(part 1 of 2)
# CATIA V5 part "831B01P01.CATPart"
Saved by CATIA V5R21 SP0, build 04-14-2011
Part number: 831B01P01
Bounding box of the stored display mesh (mm): x -76.5 to 76.5, y -25.54 to 25.54, z -13.238 to 6.5
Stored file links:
  C:\Users\ALI OZGUN\Desktop\alhan\831B01P01.CATPart
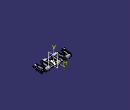
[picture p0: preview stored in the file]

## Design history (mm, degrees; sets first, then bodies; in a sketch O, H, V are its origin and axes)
Set1
  Extract1: ExtractElem start face of Pad3
  Extrapol1: ToExtrapol edge of Extract1, Support Extract1, Length 134
  Plane1: stored without definition
  Plane2: stored without definition
Body1 (main body)
  Sketch1 on yz-plane, origin (0, 0, 0), H (0, 1, 0), V (0, 0, 1)
    construction line L1 (-19.05, 0) -> (19.05, 0)
    point P1 (-19.05, 0)
    point P2 (19.05, 0)
    line L2 (-19.05, 6.5) -> (19.05, 6.5)
    line L3 (19.05, -6.5) -> (-19.05, -6.5)
    arc A1 centre (19.05, 0) radius 6.5 from (19.05, 6.5) to (19.05, -6.5) cw
    arc A2 centre (-19.05, 0) radius 6.5 from (-19.05, -6.5) to (-19.05, 6.5) cw
    circle A3 centre (19.05, 0) radius 3.25
    circle A4 centre (-19.05, 0) radius 3.25
    distance L1 L2 = 6.5
    length L1 = 38.1
    distance P2 V = 19.05
    radius A3 = 3.25
    radius A4 = 3.25
    coincidence: P1 H
    horizontal: L1 H
    tangency: A1 L2, A2 L2, A1 L3, A2 L3
  Pad1: profile Sketch1, direction (1, 0, 0), length 76.5, mirrored extent
  Sketch2 on face of Pad1 from Sketch1.L2, origin (0, 0, 6.5), H (1, 0, 0), V (0, 1, 0)
    line L1 (38, -14) -> (64, -14)
    line L2 (64, -14) -> (64, -36.0786)
    line L3 (64, -36.0786) -> (38, -36.0786)
    line L4 (38, -36.0786) -> (38, -14)
    line L5 (-13, -14) -> (13, -14)
    line L6 (13, -14) -> (13, -36.0786)
    line L7 (13, -36.0786) -> (-13, -36.0786)
    line L8 (-13, -36.0786) -> (-13, -14)
    point P7 (13, -36.0786)
    line L9 (-64, -14) -> (-38, -14)
    line L10 (-38, -14) -> (-38, -32.269)
    line L11 (-38, -32.269) -> (-64, -32.269)
    line L12 (-64, -32.269) -> (-64, -14)
    line L13 (85.7823, 31.3847) -> (63.5, 31.3847)
    line L14 (63.5, 31.3847) -> (63.5, 14)
    line L15 (63.5, 14) -> (85.7823, 14)
    line L16 (85.7823, 14) -> (85.7823, 31.3847)
    point P17 (12.5, 31.3847)
    line L17 (12.5, 31.3847) -> (38.5, 31.3847)
    line L18 (38.5, 31.3847) -> (38.5, 14)
    line L19 (38.5, 14) -> (12.5, 14)
    line L20 (12.5, 14) -> (12.5, 31.3847)
    point P19 (38.5, 14)
    line L21 (-38.5, 32.0801) -> (-12.5, 32.0801)
    line L22 (-12.5, 32.0801) -> (-12.5, 14)
    line L23 (-12.5, 14) -> (-38.5, 14)
    line L24 (-38.5, 14) -> (-38.5, 32.0801)
    point P23 (-12.5, 14)
    line L25 (-81.4786, 33.8185) -> (-63.5, 33.8185)
    line L26 (-63.5, 33.8185) -> (-63.5, 14)
    line L27 (-63.5, 14) -> (-81.4786, 14)
    line L28 (-81.4786, 14) -> (-81.4786, 33.8185)
    point P27 (-63.5, 14)
    reference projected line E1 (76.5, 19.05) -> (76.5, -19.05) from edge [face of Pad1 from Sketch1.L2 | end face of Pad1]
    reference projected line E2 (-76.5, 19.05) -> (-76.5, -19.05) from edge [start face of Pad1 | face of Pad1 from Sketch1.L2]
    reference projected line E3 (-76.5, 19.05) -> (-76.5, -19.05) from edge [start face of Pad1 | face of Pad1 from Sketch1.L2]
    reference projected line E4 (76.5, 19.05) -> (76.5, -19.05) from edge [face of Pad1 from Sketch1.L2 | end face of Pad1]
    distance L14 E1 = 13
    distance L26 E2 = 13
    distance L12 E3 = 12.5
    distance L2 E4 = 12.5
    distance L23 L5 = 28
    distance L5 H = 14
    distance L4 L2 = 26
    distance L12 L10 = 26
    distance L10 L8 = 25
    distance L6 L4 = 25
    distance L24 L26 = 25
    distance L18 L14 = 25
    distance L26 L22 = 51
    distance L20 L18 = 26
    horizontal: L1 H, L3 H, L5 H, L7 H, L9 H, L11 H, L13 H, L15 H, L17 H, L19 H, L21 H, L23 H, L25 H, L27 H
    vertical: L2 V, L4 V, L6 V, L8 V, L10 V, L12 V, L14 V, L16 V, L18 V, L20 V, L22 V, L24 V, L26 V, L28 V
    coincidence: P7 L3, P17 L13, P19 L15, P23 L15, P27 L15, L1 L5, L9 L5
  Pocket1: profile Sketch2, direction (0, 0, -1), length 53.5
  Sketch3 on end face of Pad1, origin (76.5, 0, 0), H (0, 1, 0), V (0, 0, 1)
    projected arc E1 centre (19.05, 0) radius 6.5 from (19.05, -6.5) to (19.05, 6.5) ccw from edge [face of Pocket1 from Sketch2.L14 | face of Pad1 from Sketch1.A1]
    projected arc E2 centre (19.05, 0) radius 6.5 from (19.05, -6.5) to (13.0358, 2.4657) ccw from edge [face of Pocket1 from Sketch2.L14 | face of Pad1 from Sketch1.A1]
    point P1 (19.05, -6.5)
    projected arc E3 centre (-19.05, 0) radius 6.5 from (-19.05, 6.5) to (-19.05, -6.5) ccw from edge [face of Pad1 from Sketch1.A2 | end face of Pad1]
    projected arc E4 centre (-19.05, 0) radius 6.5 from (-13.0358, 2.4657) to (-19.05, -6.5) ccw from edge [face of Pad1 from Sketch1.A2 | end face of Pad1]
    point P4 (-19.05, -6.5)
    projected line E5 (-19.05, -6.5) -> (14, -6.5) from edge [face of Pad1 from Sketch1.L3 | end face of Pad1]
    point P5 (-19.05, -6.5)
    projected line E6 (19.05, -6.5) -> (14, -6.5) from edge [face of Pocket1 from Sketch2.L14 | face of Pad1 from Sketch1.L3]
    point P7 (19.05, -6.5)
    line L1 (-13.0358, 2.4657) -> (-11, -2.5)
    line L2 (-11, -2.5) -> (11, -2.5)
    point P10 (11, -2.5)
    line L3 (11, -2.5) -> (13.0358, 2.4657)
    distance L2 E5 = 4
    length L2 = 22
    distance P10 V = 11
    horizontal: L2 H
    tangency: L3 E1, L1 E3
    coincidence: P1 P7, P4 P5
  Pocket2: profile Sketch3, direction (-1, 0, 0), length 172.5, outer side
  Sketch4 on face of Pocket2 from Sketch3.L2, origin (0, 0, -2.5), H (1, 0, 0), V (0, 1, 0)
    projected line E1 (38, -14) -> (38, -25.55) from edge [face of Pocket2 | face of Pocket1 from Sketch2.L4]
    projected line E2 (38, -14) -> (38, -19.05) from edge [face of Pocket2 | face of Pocket1 from Sketch2.L4]
    point P1 (38, -14)
    point P2 (38, -25.55)
    projected line E3 (13, -25.55) -> (13, -14) from edge [face of Pocket2 | face of Pocket1 from Sketch2.L6]
    projected line E4 (13, -19.05) -> (13, -14) from edge [face of Pocket2 | face of Pocket1 from Sketch2.L6]
    point P3 (13, -25.55)
    point P4 (13, -14)
    projected line E5 (64, -25.55) -> (64, -14) from edge [face of Pocket2 | face of Pocket1 from Sketch2.L2]
    projected line E6 (64, -19.05) -> (64, -14) from edge [face of Pocket2 | face of Pocket1 from Sketch2.L2]
    point P5 (64, -25.55)
    point P6 (64, -14)
    projected line E7 (38.5, 14) -> (38.5, 25.55) from edge [face of Pocket2 | face of Pocket1 from Sketch2.L18]
    projected line E8 (38.5, 14) -> (38.5, 19.05) from edge [face of Pocket2 | face of Pocket1 from Sketch2.L18]
    point P7 (38.5, 14)
    point P8 (38.5, 25.55)
    projected line E9 (63.5, 14) -> (63.5, 25.55) from edge [face of Pocket1 from Sketch2.L14 | face of Pocket2]
    projected line E10 (63.5, 14) -> (63.5, 19.05) from edge [face of Pocket1 from Sketch2.L14 | face of Pocket2]
    point P9 (63.5, 14)
    point P10 (63.5, 25.55)
    projected line E11 (12.5, 25.55) -> (12.5, 14) from edge [face of Pocket2 | face of Pocket1 from Sketch2.L20]
    projected line E12 (12.5, 19.05) -> (12.5, 14) from edge [face of Pocket2 | face of Pocket1 from Sketch2.L20]
    point P11 (12.5, 25.55)
    point P12 (12.5, 14)
    offset line E13 (9.5, 25.55) -> (9.5, 14) from edge [face of Pocket2 | face of Pocket1 from Sketch2.L20]
    offset line E14 (9.5, 19.05) -> (9.5, 14) from edge [face of Pocket2 | face of Pocket1 from Sketch2.L20]
    point P13 (9.5, 25.55)
    point P14 (9.5, 14)
    offset line E15 (16, -25.55) -> (16, -14) from edge [face of Pocket2 | face of Pocket1 from Sketch2.L6]
    offset line E16 (16, -19.05) -> (16, -14) from edge [face of Pocket2 | face of Pocket1 from Sketch2.L6]
    point P15 (16, -25.55)
    point P16 (16, -14)
    offset line E17 (35, -14) -> (35, -25.55) from edge [face of Pocket2 | face of Pocket1 from Sketch2.L4]
    offset line E18 (35, -14) -> (35, -19.05) from edge [face of Pocket2 | face of Pocket1 from Sketch2.L4]
    point P17 (35, -14)
    point P18 (35, -25.55)
    offset line E19 (41.5, 14) -> (41.5, 25.55) from edge [face of Pocket2 | face of Pocket1 from Sketch2.L18]
    offset line E20 (41.5, 14) -> (41.5, 19.05) from edge [face of Pocket2 | face of Pocket1 from Sketch2.L18]
    point P19 (41.5, 14)
    point P20 (41.5, 25.55)
    offset line E21 (60.5, 14) -> (60.5, 25.55) from edge [face of Pocket1 from Sketch2.L14 | face of Pocket2]
    offset line E22 (60.5, 14) -> (60.5, 19.05) from edge [face of Pocket1 from Sketch2.L14 | face of Pocket2]
    point P21 (60.5, 14)
    point P22 (60.5, 25.55)
    offset line E23 (67, -25.55) -> (67, -14) from edge [face of Pocket2 | face of Pocket1 from Sketch2.L2]
    offset line E24 (67, -19.05) -> (67, -14) from edge [face of Pocket2 | face of Pocket1 from Sketch2.L2]
    point P23 (67, -25.55)
    point P24 (67, -14)
    line L1 (13, -14) -> (9.5, 14)
    line L2 (16, -14) -> (12.5, 14)
    line L3 (35, -14) -> (38.5, 14)
    line L4 (38, -14) -> (41.5, 14)
    line L5 (64, -14) -> (60.5, 14)
    line L6 (67, -14) -> (63.5, 14)
    projected line E25 through (0, -19.05) direction (1, 0) from axis of face of Pocket2
    projected line E26 (13, -19.05) -> (16, -19.05) from axis of face of Pocket2
    projected line E27 (64, -19.05) -> (67, -19.05) from axis of face of Pocket2
    projected line E28 (35, -19.05) -> (38, -19.05) from axis of face of Pocket2
    point P25 (-10000000, -19.05)
    point P26 (10000000, -19.05)
    point P27 (67, -19.05)
    point P28 (38, -19.05)
    point P29 (64, -19.05)
    point P30 (64, -19.05)
    point P31 (38, -19.05)
    point P32 (35, -19.05)
    point P33 (16, -19.05)
    point P34 (35, -19.05)
    point P35 (16, -19.05)
    point P36 (13, -19.05)
    point P37 (13, -19.05)
    projected line E29 through (0, 19.05) direction (1, 0) from axis of face of Pocket2
    projected line E30 (9.5, 19.05) -> (12.5, 19.05) from axis of face of Pocket2
    projected line E31 (38.5, 19.05) -> (41.5, 19.05) from axis of face of Pocket2
    projected line E32 (60.5, 19.05) -> (63.5, 19.05) from axis of face of Pocket2
    point P38 (-10000000, 19.05)
    point P39 (10000000, 19.05)
    point P40 (63.5, 19.05)
    point P41 (9.5, 19.05)
    point P42 (9.5, 19.05)
    point P43 (12.5, 19.05)
    point P44 (12.5, 19.05)
    point P45 (38.5, 19.05)
    point P46 (38.5, 19.05)
    point P47 (41.5, 19.05)
    point P48 (60.5, 19.05)
    point P49 (41.5, 19.05)
    point P50 (60.5, 19.05)
    point P51 (-10000000, -19.05)
    point P52 (10000000, -19.05)
    point P53 (-10000000, 19.05)
    point P54 (10000000, 19.05)
    construction line L7 through (0, -19.05) direction (-1, 0)
    construction line L8 through (0, 19.05) direction (-1, 0)
    point P55 (-10000000, -19.05)
    point P56 (10000000, -19.05)
    point P57 (-16, -19.05)
    point P58 (-13, -19.05)
    point P59 (-67, -19.05)
    point P60 (-64, -19.05)
    point P61 (-38, -19.05)
    point P62 (-35, -19.05)
    point P63 (-38, -25.55)
    point P64 (-38, -14)
    point P65 (-38, -19.05)
    point P66 (-13, -14)
    point P67 (-13, -25.55)
    point P68 (-13, -19.05)
    point P69 (-64, -14)
    point P70 (-64, -25.55)
    point P71 (-64, -19.05)
    point P72 (-38.5, 25.55)
    point P73 (-38.5, 14)
    point P74 (-38.5, 19.05)
    point P75 (-63.5, 25.55)
    point P76 (-63.5, 14)
    point P77 (-63.5, 19.05)
    point P78 (-12.5, 14)
    point P79 (-12.5, 25.55)
    point P80 (-12.5, 19.05)
    point P81 (-9.5, 14)
    point P82 (-9.5, 25.55)
    point P83 (-9.5, 19.05)
    point P84 (-16, -14)
    point P85 (-16, -25.55)
    point P86 (-16, -19.05)
    point P87 (-35, -25.55)
    point P88 (-35, -14)
    point P89 (-35, -19.05)
    point P90 (-41.5, 25.55)
    point P91 (-41.5, 14)
    point P92 (-41.5, 19.05)
    point P93 (-60.5, 25.55)
    point P94 (-60.5, 14)
    point P95 (-60.5, 19.05)
    point P96 (-67, -14)
    point P97 (-67, -25.55)
    line L9 (-13, -14) -> (-9.5, 14)
    line L10 (-16, -14) -> (-12.5, 14)
    line L11 (-35, -14) -> (-38.5, 14)
    line L12 (-38, -14) -> (-41.5, 14)
    line L13 (-64, -14) -> (-60.5, 14)
    line L14 (-67, -14) -> (-63.5, 14)
    point P98 (-10000000, 19.05)
    point P99 (10000000, 19.05)
    point P100 (-12.5, 19.05)
    point P101 (-9.5, 19.05)
    point P102 (-41.5, 19.05)
    point P103 (-38.5, 19.05)
    point P104 (-60.5, 19.05)
    construction line L15 through (0, -19.05) direction (-1, 0)
    line L16 (-13, -19.05) -> (-16, -19.05)
    line L17 (-64, -19.05) -> (-67, -19.05)
    line L18 (-35, -19.05) -> (-38, -19.05)
    construction line L19 (-38, -14) -> (-38, -25.55)
    line L20 (-38, -14) -> (-38, -19.05)
    construction line L21 (-13, -25.55) -> (-13, -14)
    line L22 (-13, -19.05) -> (-13, -14)
    construction line L23 (-64, -25.55) -> (-64, -14)
    line L24 (-64, -19.05) -> (-64, -14)
    construction line L25 (-38.5, 14) -> (-38.5, 25.55)
    line L26 (-38.5, 14) -> (-38.5, 19.05)
    construction line L27 (-63.5, 14) -> (-63.5, 25.55)
    line L28 (-63.5, 14) -> (-63.5, 19.05)
    construction line L29 (-12.5, 25.55) -> (-12.5, 14)
    line L30 (-12.5, 19.05) -> (-12.5, 14)
    construction line L31 (-9.5, 25.55) -> (-9.5, 14)
    line L32 (-9.5, 19.05) -> (-9.5, 14)
    construction line L33 (-16, -25.55) -> (-16, -14)
    line L34 (-16, -19.05) -> (-16, -14)
    construction line L35 (-35, -14) -> (-35, -25.55)
    line L36 (-35, -14) -> (-35, -19.05)
    construction line L37 (-41.5, 14) -> (-41.5, 25.55)
    line L38 (-41.5, 14) -> (-41.5, 19.05)
    construction line L39 (-60.5, 14) -> (-60.5, 25.55)
    line L40 (-60.5, 14) -> (-60.5, 19.05)
    construction line L41 (-67, -25.55) -> (-67, -14)
    line L42 (-67, -19.05) -> (-67, -14)
    construction line L43 through (0, 19.05) direction (-1, 0)
    line L44 (-9.5, 19.05) -> (-12.5, 19.05)
    line L45 (-38.5, 19.05) -> (-41.5, 19.05)
    line L46 (-60.5, 19.05) -> (-63.5, 19.05)
    parallelism: L2 L1, L4 L3
    coincidence: E1 P28, E5 P29, E25 P30, E25 P31, E25 P32, E15 P33, E17 P34, E25 P35, E25 P36, E3 P37, E13 P41, E29 P42, E29 P43, E11 P44, E7 P45, E29 P46, E29 P47, E29 P48, E19 P49, E21 P50, P28 P31, P29 P30, P32 P34, P33 P35, P36 P37, P41 P42, P43 P44, P45 P46, P47 P49, P48 P50
    symmetry: P26 P51 V, P25 P52 V, E25 L7 V, P39 P53 V, P38 P54 V, E29 L8 V, P26 P55 V, P25 P56 V, P33 P57 V, P37 P58 V, P27 P59 V, P29 P60 V, P28 P61 V, P34 P62 V, E25 L15 V, P2 P63 V, P1 P64 V, P31 P65 V, E1 L19 V, P4 P66 V, P3 P67 V, P36 P68 V, E3 L21 V, P6 P69 V, P5 P70 V, P30 P71 V, E5 L23 V, P8 P72 V, P7 P73 V, P46 P74 V, E7 L25 V, P10 P75 V, P9 P76 V, P40 P77 V, E9 L27 V, P12 P78 V, P11 P79 V, P43 P80 V, E11 L29 V, P14 P81 V, P13 P82 V, P42 P83 V, E13 L31 V, P16 P84 V, P15 P85 V, P35 P86 V, E15 L33 V, P18 P87 V, P17 P88 V, P32 P89 V, E17 L35 V, P20 P90 V, P19 P91 V, P47 P92 V, E19 L37 V, P22 P93 V, P21 P94 V, P48 P95 V, E21 L39 V, P24 P96 V, P23 P97 V, E23 L41 V, L1 L9 V, L2 L10 V, L3 L11 V, L4 L12 V, L5 L13 V, L6 L14 V, P39 P98 V, P38 P99 V, P44 P100 V, P41 P101 V, P49 P102 V, P45 P103 V, P50 P104 V, E29 L43 V, E25 L18 V, E25 L17 V, E25 L16 V, E1 L20 V, E3 L22 V, E5 L24 V, E7 L26 V, E9 L28 V, E11 L30 V, E13 L32 V, E15 L34 V, E17 L36 V, E19 L38 V, E21 L40 V, E23 L42 V, E29 L46 V, E29 L45 V, E29 L44 V
  Pad2: profile Sketch4, direction (0, 0, 1), length 9
  Sketch5 on yz-plane, origin (0, 0, 0), H (0, 1, 0), V (0, 0, 1)
    projected circle E1 centre (-19.05, 0) radius 3.25 from edge [end face of Pad1 | face of Pad1 from Sketch1.A4]
    circle A1 centre (19.05, 0) radius 3.25
    reference projected circle E2 centre (19.05, 0) radius 3.25 from edge [face of Pad1 from Sketch1.A3 | face of Pad2]
    coincidence: A1 E2
  Pocket3: profile Sketch5, direction (-1, 0, 0), length 95, mirrored extent
  RemoveFace1: RemoveFaces (face of Pocket2 from Sketch3.L3; face of Pocket2; face of Pocket2 from Sketch3.L3; face of Pocket2; face of Pocket2 from Sketch3.L1; face of Pocket2; face of Pocket2 from Sketch3.L1; face of Pocket2; face of Pocket2; face of Pocket2; face of Pocket2; face of Pocket2 from Sketch3.L3; face of Pocket2 from Sketch3.L3; face of Pocket2 from Sketch3.L1)
  Chamfer1: length 4, angle 45, on edge [face of Pocket1 from Sketch2.L27 | face of Pocket2 from Sketch3.L2]; edge [face of Pocket1 from Sketch2.L9 | face of Pocket2 from Sketch3.L2]; edge [face of Pocket1 from Sketch2.L19 | face of Pocket2 from Sketch3.L2]; edge [face of Pocket1 from Sketch2.L5 | face of Pocket2 from Sketch3.L2]; edge [face of Pocket1 from Sketch2.L1 | face of Pocket2 from Sketch3.L2]; edge [face of Pocket1 from Sketch2.L15 | face of Pocket2 from Sketch3.L2]; edge [face of Pocket1 from Sketch2.L23 | face of Pocket2 from Sketch3.L2]
  Sketch6 on face of Pocket2 from Sketch3.L2, origin (0, 0, -2.5), H (1, 0, 0), V (0, 1, 0)
    point P1 (63.5, 19.05)
    point P2 (63.5, 25.55)
    line L1 (-10.8063, 3.55) -> (10.8062, 3.55)
    line L2 (-10.4313, 6.55) -> (10.4312, 6.55)
    construction line L3 (-27.6701, 3.55) -> (-27.6701, 6.55)
    construction line L4 (101.9815, 3.55) -> (101.9815, 6.55)
    point P7 (61.4312, 6.55)
    line L5 (40.5688, 6.55) -> (61.4312, 6.55)
    point P8 (40.5688, 6.55)
    line L6 (40.1938, 3.55) -> (61.8062, 3.55)
    point P13 (40.1938, 3.55)
    point P14 (61.8062, 3.55)
    line L7 (64.8062, 3.55) -> (72.5, 3.55)
    point P15 (64.8062, 3.55)
    line L8 (60.875, 11) -> (61.4312, 6.55)
    point P16 (60.875, 11)
    point P17 (63.5, -10)
    line L9 (63.5, -10) -> (38.5, -10)
    point P18 (38.5, -10)
    line L10 (38.5, -10) -> (40.1938, 3.55)
    point P19 (41.125, 11)
    line L11 (41.125, 11) -> (60.875, 11)
    line L12 (15.625, -11) -> (15.0687, -6.55)
    point P20 (15.625, -11)
    point P21 (13, 10)
    line L13 (13, 10) -> (38, 10)
    point P22 (38, 10)
    line L14 (38, 10) -> (36.3063, -3.55)
    point P23 (35.375, -11)
    line L15 (35.375, -11) -> (15.625, -11)
    line L16 (9.875, 11) -> (10.4312, 6.55)
    line L17 (12.5, -10) -> (-12.5, -10)
    line L18 (-12.5, -10) -> (-10.8063, 3.55)
    line L19 (-9.875, 11) -> (9.875, 11)
    line L20 (66, -6) -> (64.8062, 3.55)
    point P28 (66.625, -11)
    construction line L21 (76.5, 3.55) -> (76.5, -6)
    point P29 (76.5, -11)
    construction line L22 (76.5, -11) -> (66.625, -11)
    construction line L23 (63.5, 19.05) -> (63.5, 25.55)
    line L24 (40.5688, 6.55) -> (41.125, 11)
    line L25 (61.8062, 3.55) -> (63.5, -10)
    line L26 (14.6937, -3.55) -> (13, 10)
    line L27 (10.8062, 3.55) -> (12.5, -10)
    line L28 (-10.4313, 6.55) -> (-9.875, 11)
    line L29 (72.5, -6) -> (66, -6)
    point P30 (76.5, -6)
    point P31 (66.625, -6)
    construction line L30 (76.5, -11) -> (76.5, -6)
    construction line L31 (66.625, -11) -> (66.625, -6)
    point P32 (66, -6)
    point P33 (76.5, 3.55)
    point P34 (76.5, -6)
    point P35 (-63.5, 25.55)
    point P36 (-63.5, 19.05)
    construction line L32 (-63.5, 19.05) -> (-63.5, 25.55)
    point P37 (-66.625, -11)
    point P38 (-76.5, -11)
    construction line L33 (-76.5, -11) -> (-66.625, -11)
    point P39 (-61.4312, 6.55)
    point P40 (-40.5688, 6.55)
    line L34 (-40.5688, 6.55) -> (-61.4312, 6.55)
    point P41 (-61.8062, 3.55)
    point P42 (-40.1938, 3.55)
    line L35 (-40.1938, 3.55) -> (-61.8062, 3.55)
    point P43 (-64.8062, 3.55)
    line L36 (-64.8062, 3.55) -> (-72.5, 3.55)
    point P44 (-60.875, 11)
    line L37 (-60.875, 11) -> (-61.4312, 6.55)
    point P45 (-38.5, -10)
    point P46 (-63.5, -10)
    line L38 (-63.5, -10) -> (-38.5, -10)
    line L39 (-38.5, -10) -> (-40.1938, 3.55)
    point P47 (-41.125, 11)
    line L40 (-41.125, 11) -> (-60.875, 11)
    point P48 (-15.625, -11)
    line L41 (-15.625, -11) -> (-15.0687, -6.55)
    point P49 (-38, 10)
    point P50 (-13, 10)
    line L42 (-13, 10) -> (-38, 10)
    line L43 (-38, 10) -> (-36.3063, -3.55)
    point P51 (-35.375, -11)
    line L44 (-35.375, -11) -> (-15.625, -11)
    point P52 (-66, -6)
    line L45 (-66, -6) -> (-64.8062, 3.55)
    line L46 (-40.5688, 6.55) -> (-41.125, 11)
    line L47 (-61.8062, 3.55) -> (-63.5, -10)
    line L48 (-14.6937, -3.55) -> (-13, 10)
    line L49 (-72.5, -6) -> (-66, -6)
    line L50 (72.5, 3.55) -> (72.5, -6)
    point P53 (72.5, 3.55)
    point P54 (72.5, -6)
    construction line L51 (76.5, 3.55) -> (72.5, 3.55)
    construction line L52 (76.5, -6) -> (72.5, -6)
    point P55 (72.5, 3.55)
    point P56 (72.5, -6)
    point P57 (-72.5, -6)
    point P58 (-72.5, 3.55)
    line L53 (-72.5, 3.55) -> (-72.5, -6)
    line L54 (-15.0687, -6.55) -> (-35.9313, -6.55)
    line L55 (-14.6937, -3.55) -> (-36.3063, -3.55)
    line L56 (15.0687, -6.55) -> (35.9313, -6.55)
    line L57 (14.6937, -3.55) -> (36.3063, -3.55)
    line L58 (35.9313, -6.55) -> (35.375, -11)
    line L59 (-35.9313, -6.55) -> (-35.375, -11)
    distance P2 L1 = 22
    distance L1 L2 = 3
    distance L22 L29 = 5
    distance L21 L50 = 4
    horizontal: L1 H, L6 H, L7 H
    perpendicularity: L3 L1, L3 L2, L4 L1, L4 L2, L30 L22, L30 L29, L31 L22, L31 L29, L51 L21, L51 L50, L52 L21, L52 L50
    coincidence: L2 L5, L6 L7, L10 L24, L8 L25, L12 L26, L16 L27, L18 L28, P28 L20, P31 L29, P29 L21, P30 L29, P33 L7, P53 L50, P34 L29, P54 L50
    fix: L23, P2, L22
    symmetry: P2 P35 V, P1 P36 V, L23 L32 V, P28 P37 V, P29 P38 V, L22 L33 V, P7 P39 V, P8 P40 V, L5 L34 V, P14 P41 V, P13 P42 V, L6 L35 V, P15 P43 V, L7 L36 V, P16 P44 V, L8 L37 V, P18 P45 V, P17 P46 V, L9 L38 V, L10 L39 V, P19 P47 V, L11 L40 V, P20 P48 V, L12 L41 V, P22 P49 V, P21 P50 V, L13 L42 V, L14 L43 V, P23 P51 V, L15 L44 V, P32 P52 V, L20 L45 V, L24 L46 V, L25 L47 V, L26 L48 V, L29 L49 V, P56 P57 V, P55 P58 V, L50 L53 V
  Pocket4: profile Sketch6, direction (0, 0, -1), length 9, mirrored extent
  Body2
    Sketch7 on face of Pocket2, origin (0, 0, -6.5), H (1, 0, 0), V (0, -1, 0)
      point P1 (-60.75, 15)
      line L1 (-60.75, 15) -> (-54.25, 15)
      line L2 (-54.25, 15) -> (-54.25, -15)
      line L3 (-54.25, -15) -> (-60.75, -15)
      line L4 (-60.75, -15) -> (-60.75, 15)
      point P2 (-54.25, 15)
      point P3 (-54.25, -15)
      point P4 (-60.75, -15)
      point P5 (-47.75, 15)
      line L5 (-47.75, 15) -> (-41.25, 15)
      line L6 (-41.25, 15) -> (-41.25, -15)
      line L7 (-41.25, -15) -> (-47.75, -15)
      line L8 (-47.75, -15) -> (-47.75, 15)
      point P6 (-41.25, 15)
      point P7 (-41.25, -15)
      point P8 (-47.75, -15)
      reference projected line E1 (-64, 19.05) -> (-64, 14) from edge [face of Pocket2 | face of Pad2]
      reference projected line E2 (-38, 19.05) -> (-38, 14) from edge [face of Pad2 | face of Pocket2]
      point P9 (-38, 19.05)
      point P10 (-38, 14)
      point P11 (-15.25, 15)
      point P12 (-21.75, 15)
      point P13 (-21.75, -15)
      point P14 (-15.25, -15)
      point P15 (-28.25, 15)
      point P16 (-34.75, 15)
      point P17 (-34.75, -15)
      point P18 (-28.25, -15)
      line L9 (-15.25, 15) -> (-21.75, 15)
      line L10 (-21.75, 15) -> (-21.75, -15)
      line L11 (-21.75, -15) -> (-15.25, -15)
      line L12 (-15.25, -15) -> (-15.25, 15)
      line L13 (-28.25, 15) -> (-34.75, 15)
      line L14 (-34.75, 15) -> (-34.75, -15)
      line L15 (-34.75, -15) -> (-28.25, -15)
      line L16 (-28.25, -15) -> (-28.25, 15)
      reference projected line E3 (-13, 19.05) -> (-13, 14) from edge [face of Pocket2 | face of Pad2]
      point P19 (-13, 19.05)
      point P20 (-13, 14)
      point P21 (-10.75, 15)
      point P22 (-4.25, 15)
      point P23 (-4.25, -15)
      point P24 (-10.75, -15)
      construction line L17 (-10.75, 15) -> (-4.25, 15)
      construction line L18 (-4.25, 15) -> (-4.25, -15)
      construction line L19 (-4.25, -15) -> (-10.75, -15)
      construction line L20 (-10.75, -15) -> (-10.75, 15)
      point P25 (60.75, 15)
      point P26 (54.25, 15)
      point P27 (54.25, -15)
      point P28 (60.75, -15)
      point P29 (47.75, 15)
      point P30 (41.25, 15)
      point P31 (41.25, -15)
      point P32 (47.75, -15)
      point P33 (38, 14)
      point P34 (38, 19.05)
      point P35 (15.25, 15)
      point P36 (21.75, 15)
      point P37 (21.75, -15)
      point P38 (15.25, -15)
      point P39 (28.25, 15)
      point P40 (34.75, 15)
      point P41 (34.75, -15)
      point P42 (28.25, -15)
      point P43 (13, 14)
      point P44 (13, 19.05)
      point P45 (10.75, 15)
      point P46 (4.25, 15)
      point P47 (4.25, -15)
      point P48 (10.75, -15)
      line L21 (60.75, 15) -> (54.25, 15)
      line L22 (54.25, 15) -> (54.25, -15)
      line L23 (54.25, -15) -> (60.75, -15)
      line L24 (60.75, -15) -> (60.75, 15)
      line L25 (47.75, 15) -> (41.25, 15)
      line L26 (41.25, 15) -> (41.25, -15)
      line L27 (41.25, -15) -> (47.75, -15)
      line L28 (47.75, -15) -> (47.75, 15)
      line L29 (15.25, 15) -> (21.75, 15)
      line L30 (21.75, 15) -> (21.75, -15)
      line L31 (21.75, -15) -> (15.25, -15)
      line L32 (15.25, -15) -> (15.25, 15)
      line L33 (28.25, 15) -> (34.75, 15)
      line L34 (34.75, 15) -> (34.75, -15)
      line L35 (34.75, -15) -> (28.25, -15)
      line L36 (28.25, -15) -> (28.25, 15)
      construction line L37 (10.75, 15) -> (4.25, 15)
      construction line L38 (4.25, 15) -> (4.25, -15)
      construction line L39 (4.25, -15) -> (10.75, -15)
      construction line L40 (10.75, -15) -> (10.75, 15)
      construction line L41 (38, 19.05) -> (38, 14)
      construction line L42 (13, 19.05) -> (13, 14)
      point P49 (-74.2, 15)
      line L43 (-74.2, 15) -> (-67.7, 15)
      line L44 (-67.7, 15) -> (-67.7, -15)
      line L45 (-67.7, -15) -> (-74.2, -15)
      line L46 (-74.2, -15) -> (-74.2, 15)
      point P50 (-67.7, 15)
      point P51 (-67.7, -15)
      point P52 (-74.2, -15)
      reference projected line E4 (-76.5, 19.05) -> (-76.5, -14) from edge [start face of Pad1 | face of Pocket2]
      point P53 (74.2, 15)
      point P54 (67.7, 15)
      point P55 (67.7, -15)
      point P56 (74.2, -15)
      line L47 (74.2, 15) -> (67.7, 15)
      line L48 (67.7, 15) -> (67.7, -15)
      line L49 (67.7, -15) -> (74.2, -15)
      line L50 (74.2, -15) -> (74.2, 15)
      point P57 (-9.75, 15)
      line L51 (-9.75, 15) -> (-3.25, 15)
      line L52 (-3.25, 15) -> (-3.25, -15)
      line L53 (-3.25, -15) -> (-9.75, -15)
      line L54 (-9.75, -15) -> (-9.75, 15)
      point P58 (-3.25, 15)
      point P59 (-3.25, -15)
      point P60 (-9.75, -15)
      point P61 (9.75, -15)
      point P62 (3.25, -15)
      point P63 (3.25, 15)
      point P64 (9.75, 15)
      line L55 (9.75, -15) -> (9.75, 15)
      line L56 (3.25, -15) -> (9.75, -15)
      line L57 (3.25, 15) -> (3.25, -15)
      line L58 (9.75, 15) -> (3.25, 15)
      length L1 = 6.5
      distance L8 L6 = 6.5
      distance L6 L4 = 19.5
      distance L4 E1 = 3.25
      distance L7 L5 = 30
      distance L5 H = 15
      length L43 = 6.5
      distance L44 E4 = 8.8
      distance L54 L52 = 6.5
      distance L52 V = 3.25
      horizontal: L1 H, L3 H, L5 H, L7 H, L43 H, L45 H, L51 H, L53 H
      vertical: L2 V, L4 V, L6 V, L8 V, L44 V, L46 V, L52 V, L54 V
      coincidence: P5 L1, P7 L3, P49 L37, P51 L39, P57 L17, P59 L45
      symmetry: P1 P11 E2, P2 P12 E2, P3 P13 E2, P4 P14 E2, P5 P15 E2, P6 P16 E2, P7 P17 E2, P8 P18 E2, L1 L9 E2, L2 L10 E2, L3 L11 E2, L4 L12 E2, L5 L13 E2, L6 L14 E2, L7 L15 E2, L8 L16 E2, P11 P21 E3, P12 P22 E3, P13 P23 E3, P14 P24 E3, L9 L17 E3, L10 L18 E3, L11 L19 E3, L12 L20 E3, P1 P25 V, P2 P26 V, P3 P27 V, P4 P28 V, P5 P29 V, P6 P30 V, P7 P31 V, P8 P32 V, P10 P33 V, P9 P34 V, E2 L41 V, P11 P35 V, P12 P36 V, P13 P37 V, P14 P38 V, P15 P39 V, P16 P40 V, P17 P41 V, P18 P42 V, P20 P43 V, P19 P44 V, E3 L42 V, P21 P45 V, P22 P46 V, P23 P47 V, P24 P48 V, L1 L21 V, L2 L22 V, L3 L23 V, L4 L24 V, L5 L25 V, L6 L26 V, L7 L27 V, L8 L28 V, L9 L29 V, L10 L30 V, L11 L31 V, L12 L32 V, L13 L33 V, L14 L34 V, L15 L35 V, L16 L36 V, L17 L37 V, L18 L38 V, L19 L39 V, L20 L40 V, P49 P53 V, P50 P54 V, P51 P55 V, P52 P56 V, L43 L47 V, L44 L48 V, L45 L49 V, L46 L50 V, P60 P61 V, P59 P62 V, P58 P63 V, P57 P64 V, L54 L55 V, L53 L56 V, L52 L57 V, L51 L58 V
    Pad3: profile Sketch7, direction (0, 0, -1), length 6.5
    Align1: SewingRemoveFace face of Pad3 from Sketch7.L35, SplitPlane face of Chamfer1
    Align2: SewingRemoveFace face of Pad3 from Sketch7.L31, SplitPlane face of Chamfer1
    Align3: SewingRemoveFace face of Pad3 from Sketch7.L49, SplitPlane face of Chamfer1
    Align4: SewingRemoveFace face of Pad3 from Sketch7.L11, SplitPlane face of Chamfer1
    Align5: SewingRemoveFace face of Pad3 from Sketch7.L15, SplitPlane face of Chamfer1
    Align6: SewingRemoveFace face of Pad3 from Sketch7.L45, SplitPlane face of Chamfer1
    Align7: SewingRemoveFace face of Pad3 from Sketch7.L1, SplitPlane face of Chamfer1
    Align8: SewingRemoveFace face of Pad3 from Sketch7.L5, SplitPlane face of Chamfer1
    Align9: SewingRemoveFace face of Pad3 from Sketch7.L51, SplitPlane face of Chamfer1
    Align10: SewingRemoveFace face of Pad3 from Sketch7.L58, SplitPlane face of Chamfer1
    Align11: SewingRemoveFace face of Pad3 from Sketch7.L21, SplitPlane face of Chamfer1
    Align12: SewingRemoveFace face of Pad3 from Sketch7.L25, SplitPlane face of Chamfer1
    Draft1: Angle 45, Neutral Extrapol1, PullDir Extrapol1, SupportToDraft (face of Pad3 from Sketch7.L43; face of Pad3 from Sketch7.L13; face of Pad3 from Sketch7.L9; face of Pad3 from Sketch7.L29; face of Pad3 from Sketch7.L33; face of Pad3 from Sketch7.L47)
    Draft2: Angle 45, Neutral Extrapol1, PullDir Extrapol1, SupportToDraft (face of Pad3 from Sketch7.L7; face of Pad3 from Sketch7.L3; face of Pad3 from Sketch7.L27; face of Pad3 from Sketch7.L23; face of Pad3 from Sketch7.L53; face of Pad3 from Sketch7.L56)
    Thickness1: Face (face of Pad3 from Sketch7.L47; face of Pad3 from Sketch7.L33; face of Pad3 from Sketch7.L29; face of Pad3 from Sketch7.L9; face of Pad3 from Sketch7.L13; face of Pad3 from Sketch7.L43; face of Pad3 from Sketch7.L23; face of Pad3 from Sketch7.L27; face of Pad3 from Sketch7.L56; face of Pad3 from Sketch7.L53; face of Pad3 from Sketch7.L7; face of Pad3 from Sketch7.L3), Thickness 2
    Sketch8 on end face of Pad3, origin (0, 0, -13), H (1, 0, 0), V (0, -1, 0)
      construction line L1 (-57.5, 32.3998) -> (-57.5, 10.4716)
      line L2 (-56.2, 32.3998) -> (-56.2, 10.4716)
      line L3 (-58.8, 10.4716) -> (-58.8, 32.3998)
      arc A1 centre (-57.5, 10.4716) radius 1.3 from (-56.2, 10.4716) to (-58.8, 10.4716) cw
      arc A2 centre (-57.5, 32.3998) radius 1.3 from (-58.8, 32.3998) to (-56.2, 32.3998) cw
      point P3 (-56.2, 32.3998)
      point P4 (-56.2, 10.4716)
      point P5 (-58.8, 10.4716)
      point P6 (-58.8, 32.3998)
      construction line L4 (-57.5, 4.8716) -> (-57.5, -8.5284)
      line L5 (-56.2, 4.8716) -> (-56.2, -8.5284)
      line L6 (-58.8, -8.5284) -> (-58.8, 4.8716)
      arc A3 centre (-57.5, -8.5284) radius 1.3 from (-56.2, -8.5284) to (-58.8, -8.5284) cw
      arc A4 centre (-57.5, 4.8716) radius 1.3 from (-58.8, 4.8716) to (-56.2, 4.8716) cw
      point P9 (-56.2, 4.8716)
      point P10 (-56.2, -8.5284)
      point P11 (-58.8, -8.5284)
      point P12 (-58.8, 4.8716)
      reference projected line E1 (-54.25, -15) -> (-54.25, 15) from edge [face of Pad3 from Sketch7.L2 | end face of Pad3]
      construction line L7 (-51, 29.4802) -> (-51, -21.867)
      point P13 (-51, 29.4802)
      reference projected line E2 (-47.75, 15) -> (-47.75, -15) from edge [face of Pad3 from Sketch7.L8 | end face of Pad3]
      construction line L8 (-44.5, 32.3998) -> (-44.5, 10.4716)
      construction line L9 (-44.5, 4.8716) -> (-44.5, -8.5284)
      point P19 (-45.8, 10.4716)
      point P20 (-45.8, 32.3998)
      line L10 (-45.8, 32.3998) -> (-45.8, 10.4716)
      point P21 (-43.2, 32.3998)
      point P22 (-43.2, 10.4716)
      line L11 (-43.2, 10.4716) -> (-43.2, 32.3998)
      arc A5 centre (-44.5, 10.4716) radius 1.3 from (-45.8, 10.4716) to (-43.2, 10.4716) ccw
      arc A6 centre (-44.5, 32.3998) radius 1.3 from (-43.2, 32.3998) to (-45.8, 32.3998) ccw
      point P23 (-45.8, -8.5284)
      point P24 (-45.8, 4.8716)
      line L12 (-45.8, 4.8716) -> (-45.8, -8.5284)
      point P25 (-43.2, 4.8716)
      point P26 (-43.2, -8.5284)
      line L13 (-43.2, -8.5284) -> (-43.2, 4.8716)
      arc A7 centre (-44.5, -8.5284) radius 1.3 from (-45.8, -8.5284) to (-43.2, -8.5284) ccw
      arc A8 centre (-44.5, 4.8716) radius 1.3 from (-43.2, 4.8716) to (-45.8, 4.8716) ccw
      construction line L14 (57.5, 32.3998) -> (57.5, 10.4716)
      point P29 (56.2, 32.3998)
      point P30 (56.2, 10.4716)
      point P31 (58.8, 10.4716)
      point P32 (58.8, 32.3998)
      construction line L15 (57.5, 4.8716) -> (57.5, -8.5284)
      point P35 (56.2, 4.8716)
      point P36 (56.2, -8.5284)
      point P37 (58.8, -8.5284)
      point P38 (58.8, 4.8716)
      point P39 (51, 29.4802)
      construction line L16 (44.5, 32.3998) -> (44.5, 10.4716)
      construction line L17 (44.5, 4.8716) -> (44.5, -8.5284)
      point P44 (45.8, 10.4716)
      point P45 (45.8, 32.3998)
      point P46 (43.2, 32.3998)
      point P47 (43.2, 10.4716)
      point P48 (45.8, -8.5284)
      point P49 (45.8, 4.8716)
      point P50 (43.2, 4.8716)
      point P51 (43.2, -8.5284)
      line L18 (56.2, 32.3998) -> (56.2, 10.4716)
      line L19 (58.8, 10.4716) -> (58.8, 32.3998)
      arc A9 centre (57.5, 10.4716) radius 1.3 from (56.2, 10.4716) to (58.8, 10.4716) ccw
      arc A10 centre (57.5, 32.3998) radius 1.3 from (58.8, 32.3998) to (56.2, 32.3998) ccw
      line L20 (56.2, 4.8716) -> (56.2, -8.5284)
      line L21 (58.8, -8.5284) -> (58.8, 4.8716)
      arc A11 centre (57.5, -8.5284) radius 1.3 from (56.2, -8.5284) to (58.8, -8.5284) ccw
      arc A12 centre (57.5, 4.8716) radius 1.3 from (58.8, 4.8716) to (56.2, 4.8716) ccw
      line L22 (45.8, 32.3998) -> (45.8, 10.4716)
      line L23 (43.2, 10.4716) -> (43.2, 32.3998)
      arc A13 centre (44.5, 10.4716) radius 1.3 from (45.8, 10.4716) to (43.2, 10.4716) cw
      arc A14 centre (44.5, 32.3998) radius 1.3 from (43.2, 32.3998) to (45.8, 32.3998) cw
      line L24 (45.8, 4.8716) -> (45.8, -8.5284)
      line L25 (43.2, -8.5284) -> (43.2, 4.8716)
      arc A15 centre (44.5, -8.5284) radius 1.3 from (45.8, -8.5284) to (43.2, -8.5284) cw
      arc A16 centre (44.5, 4.8716) radius 1.3 from (43.2, 4.8716) to (45.8, 4.8716) cw
      construction line L26 (-25.5, 35.6086) -> (-25.5, -36.7002)
      point P53 (-25.5, -36.7002)
      reference projected line E3 (-9.75, 15) -> (-9.75, -15) from edge [face of Pad3 from Sketch7.L54 | end face of Pad3]
      construction line L27 (6.5, 32.3998) -> (6.5, 10.4716)
      construction line L28 (6.5, 4.8716) -> (6.5, -8.5284)
      construction line L29 (-6.5, 32.3998) -> (-6.5, 10.4716)
      construction line L30 (-6.5, 4.8716) -> (-6.5, -8.5284)
      point P62 (5.2, 10.4716)
      point P63 (5.2, 32.3998)
      line L31 (5.2, 32.3998) -> (5.2, 10.4716)
      point P64 (7.8, 32.3998)
      point P65 (7.8, 10.4716)
      line L32 (7.8, 10.4716) -> (7.8, 32.3998)
      arc A17 centre (6.5, 10.4716) radius 1.3 from (5.2, 10.4716) to (7.8, 10.4716) ccw
      arc A18 centre (6.5, 32.3998) radius 1.3 from (7.8, 32.3998) to (5.2, 32.3998) ccw
      point P66 (5.2, -8.5284)
      point P67 (5.2, 4.8716)
      line L33 (5.2, 4.8716) -> (5.2, -8.5284)
      point P68 (7.8, 4.8716)
      point P69 (7.8, -8.5284)
      line L34 (7.8, -8.5284) -> (7.8, 4.8716)
      arc A19 centre (6.5, -8.5284) radius 1.3 from (5.2, -8.5284) to (7.8, -8.5284) ccw
      arc A20 centre (6.5, 4.8716) radius 1.3 from (7.8, 4.8716) to (5.2, 4.8716) ccw
      point P70 (-5.2, 10.4716)
      point P71 (-5.2, 32.3998)
      line L35 (-5.2, 32.3998) -> (-5.2, 10.4716)
      point P72 (-7.8, 32.3998)
      point P73 (-7.8, 10.4716)
      line L36 (-7.8, 10.4716) -> (-7.8, 32.3998)
      arc A21 centre (-6.5, 10.4716) radius 1.3 from (-5.2, 10.4716) to (-7.8, 10.4716) cw
      arc A22 centre (-6.5, 32.3998) radius 1.3 from (-7.8, 32.3998) to (-5.2, 32.3998) cw
      point P74 (-5.2, -8.5284)
      point P75 (-5.2, 4.8716)
      line L37 (-5.2, 4.8716) -> (-5.2, -8.5284)
      point P76 (-7.8, 4.8716)
      point P77 (-7.8, -8.5284)
      line L38 (-7.8, -8.5284) -> (-7.8, 4.8716)
      arc A23 centre (-6.5, -8.5284) radius 1.3 from (-5.2, -8.5284) to (-7.8, -8.5284) cw
      arc A24 centre (-6.5, 4.8716) radius 1.3 from (-7.8, 4.8716) to (-5.2, 4.8716) cw
      axis line L39 (-38, 43.1227) -> (-38, -25.9192)
      reference projected line E4 (-34.75, 15) -> (-34.75, -15) from edge [face of Pad3 from Sketch7.L14 | end face of Pad3]
      reference projected line E5 (-34.75, 8.5) -> (-34.75, 15) from edge [face of Pad3 from Sketch7.L13 | face of Pad3 from Sketch7.L14]
      reference projected line E6 (-41.25, -15) -> (-41.25, 15) from edge [face of Pad3 from Sketch7.L6 | end face of Pad3]
      construction line L40 (-18.5, -32.3998) -> (-18.5, -10.4716)
      point P82 (-18.5, 8.5284)
      construction line L41 (-18.5, -4.8716) -> (-18.5, 8.5284)
      construction line L42 (-31.5, -29.4713) -> (-31.5, -10.4716)
      point P86 (-31.5, 8.5284)
      construction line L43 (-31.5, -4.8716) -> (-31.5, 8.5284)
      point P88 (-19.8, -10.4716)
      point P89 (-19.8, -32.3998)
      line L44 (-19.8, -32.3998) -> (-19.8, -10.4716)
      point P90 (-17.2, -32.3998)
      point P91 (-17.2, -10.4716)
      line L45 (-17.2, -10.4716) -> (-17.2, -32.3998)
      arc A25 centre (-18.5, -10.4716) radius 1.3 from (-19.8, -10.4716) to (-17.2, -10.4716) cw
      arc A26 centre (-18.5, -32.3998) radius 1.3 from (-17.2, -32.3998) to (-19.8, -32.3998) cw
      point P92 (-19.8, 8.5284)
      point P93 (-19.8, -4.8716)
      line L46 (-19.8, -4.8716) -> (-19.8, 8.5284)
      point P94 (-17.2, -4.8716)
      point P95 (-17.2, 8.5284)
      line L47 (-17.2, 8.5284) -> (-17.2, -4.8716)
      arc A27 centre (-18.5, 8.5284) radius 1.3 from (-19.8, 8.5284) to (-17.2, 8.5284) cw
      arc A28 centre (-18.5, -4.8716) radius 1.3 from (-17.2, -4.8716) to (-19.8, -4.8716) cw
      point P96 (-30.2, -10.4716)
      point P97 (-30.2, -29.4713)
      line L48 (-30.2, -29.4713) -> (-30.2, -10.4716)
      point P98 (-32.8, -29.4713)
      point P99 (-32.8, -10.4716)
      line L49 (-32.8, -10.4716) -> (-32.8, -29.4713)
      arc A29 centre (-31.5, -10.4716) radius 1.3 from (-30.2, -10.4716) to (-32.8, -10.4716) ccw
      arc A30 centre (-31.5, -29.4713) radius 1.3 from (-32.8, -29.4713) to (-30.2, -29.4713) ccw
      point P100 (-30.2, 8.5284)
      point P101 (-30.2, -4.8716)
      line L50 (-30.2, -4.8716) -> (-30.2, 8.5284)
      point P102 (-32.8, -4.8716)
      point P103 (-32.8, 8.5284)
      line L51 (-32.8, 8.5284) -> (-32.8, -4.8716)
      arc A31 centre (-31.5, 8.5284) radius 1.3 from (-30.2, 8.5284) to (-32.8, 8.5284) ccw
      arc A32 centre (-31.5, -4.8716) radius 1.3 from (-32.8, -4.8716) to (-30.2, -4.8716) ccw
      point P104 (25.5, -36.7002)
      construction line L52 (18.5, -32.3998) -> (18.5, -10.4716)
      construction line L53 (18.5, -4.8716) -> (18.5, 8.5284)
      construction line L54 (31.5, -29.4713) -> (31.5, -10.4716)
      construction line L55 (31.5, -4.8716) -> (31.5, 8.5284)
      point P113 (19.8, -10.4716)
      point P114 (19.8, -32.3998)
      point P115 (17.2, -32.3998)
      point P116 (17.2, -10.4716)
      point P117 (19.8, 8.5284)
      point P118 (19.8, -4.8716)
      point P119 (17.2, -4.8716)
      point P120 (17.2, 8.5284)
      point P121 (30.2, -10.4716)
      point P122 (30.2, -29.4713)
      point P123 (32.8, -29.4713)
      point P124 (32.8, -10.4716)
      point P125 (30.2, 8.5284)
      point P126 (30.2, -4.8716)
      point P127 (32.8, -4.8716)
      point P128 (32.8, 8.5284)
      line L56 (19.8, -32.3998) -> (19.8, -10.4716)
      line L57 (17.2, -10.4716) -> (17.2, -32.3998)
      arc A33 centre (18.5, -10.4716) radius 1.3 from (19.8, -10.4716) to (17.2, -10.4716) ccw
      arc A34 centre (18.5, -32.3998) radius 1.3 from (17.2, -32.3998) to (19.8, -32.3998) ccw
      line L58 (19.8, -4.8716) -> (19.8, 8.5284)
      line L59 (17.2, 8.5284) -> (17.2, -4.8716)
      arc A35 centre (18.5, 8.5284) radius 1.3 from (19.8, 8.5284) to (17.2, 8.5284) ccw
      arc A36 centre (18.5, -4.8716) radius 1.3 from (17.2, -4.8716) to (19.8, -4.8716) ccw
      line L60 (30.2, -29.4713) -> (30.2, -10.4716)
      line L61 (32.8, -10.4716) -> (32.8, -29.4713)
      arc A37 centre (31.5, -10.4716) radius 1.3 from (30.2, -10.4716) to (32.8, -10.4716) cw
      arc A38 centre (31.5, -29.4713) radius 1.3 from (32.8, -29.4713) to (30.2, -29.4713) cw
      line L62 (30.2, -4.8716) -> (30.2, 8.5284)
      line L63 (32.8, 8.5284) -> (32.8, -4.8716)
      arc A39 centre (31.5, 8.5284) radius 1.3 from (30.2, 8.5284) to (32.8, 8.5284) cw
      arc A40 centre (31.5, -4.8716) radius 1.3 from (32.8, -4.8716) to (30.2, -4.8716) cw
      construction line L64 (-71.077, -29.4713) -> (-71.077, -10.4716)
      construction line L65 (-71.077, -4.8716) -> (-71.077, 8.5284)
      point P133 (-69.777, -10.4716)
      point P134 (-69.777, -29.4713)
      point P135 (-72.377, -29.4713)
      point P136 (-72.377, -10.4716)
      point P137 (-69.777, 8.5284)
      point P138 (-69.777, -4.8716)
      point P139 (-72.377, -4.8716)
      point P140 (-72.377, 8.5284)
      line L66 (-69.777, -29.4713) -> (-69.777, -10.4716)
      line L67 (-72.377, -10.4716) -> (-72.377, -29.4713)
      arc A41 centre (-71.077, -10.4716) radius 1.3 from (-69.777, -10.4716) to (-72.377, -10.4716) ccw
      arc A42 centre (-71.077, -29.4713) radius 1.3 from (-72.377, -29.4713) to (-69.777, -29.4713) ccw
      line L68 (-69.777, -4.8716) -> (-69.777, 8.5284)
      line L69 (-72.377, 8.5284) -> (-72.377, -4.8716)
      arc A43 centre (-71.077, 8.5284) radius 1.3 from (-69.777, 8.5284) to (-72.377, 8.5284) ccw
      arc A44 centre (-71.077, -4.8716) radius 1.3 from (-72.377, -4.8716) to (-69.777, -4.8716) ccw
      construction line L70 (71.077, -29.4713) -> (71.077, -10.4716)
      construction line L71 (71.077, -4.8716) -> (71.077, 8.5284)
      point P145 (69.777, -10.4716)
      point P146 (69.777, -29.4713)
      point P147 (72.377, -29.4713)
      point P148 (72.377, -10.4716)
      point P149 (69.777, 8.5284)
      point P150 (69.777, -4.8716)
      point P151 (72.377, -4.8716)
      point P152 (72.377, 8.5284)
      line L72 (69.777, -29.4713) -> (69.777, -10.4716)
      line L73 (72.377, -10.4716) -> (72.377, -29.4713)
      arc A45 centre (71.077, -10.4716) radius 1.3 from (69.777, -10.4716) to (72.377, -10.4716) cw
      arc A46 centre (71.077, -29.4713) radius 1.3 from (72.377, -29.4713) to (69.777, -29.4713) cw
      line L74 (69.777, -4.8716) -> (69.777, 8.5284)
      line L75 (72.377, 8.5284) -> (72.377, -4.8716)
      arc A47 centre (71.077, 8.5284) radius 1.3 from (69.777, 8.5284) to (72.377, 8.5284) cw
      arc A48 centre (71.077, -4.8716) radius 1.3 from (72.377, -4.8716) to (69.777, -4.8716) cw
      reference projected line E7 (-60.75, -11.3284) -> (-54.25, -11.3284) from edge [face of Pad3 from Sketch7.L3 | end face of Pad3]
      reference projected line E8 (-34.75, -15) -> (-34.75, 15) from edge [end face of Pad3 | face of Pad3 from Sketch7.L14]
      reference intersected line E9 (-34.75, 11.3284) -> (-28.25, 11.3284) from face of Pad3 from Sketch7.L13
      reference projected line E10 (-15.25, 15) -> (-15.25, -15) from edge [end face of Pad3 | face of Pad3 from Sketch7.L12]
      reference projected line E11 (-74.2, 11.3284) -> (-67.7, 11.3284) from edge [end face of Pad3 | face of Pad3 from Sketch7.L43]
      distance L4 L5 = 1.3
      distance L4 E1 = 3.25
      distance A4 A3 = 16
      distance A1 A4 = 3
      distance L5 L2 = 0
      distance L7 E2 = 3.25
      distance L26 E3 = 15.75
      distance L39 E4 = 3.25
      distance E5 E6 = 6.5 (reference)
      distance A3 E7 = 1.5
      distance L49 E8 = 1.95
      distance L49 L42 = 1.3
      length L43 = 13.4
      distance A31 E9 = 1.5
      distance A32 A31 = 16
      distance A32 A29 = 3
      distance P82 P86 = 13
      distance P82 P86 V = 0
      distance L44 L45 = 2.6
      distance L40 E10 = 3.25
      distance A28 A25 = 3
      length L41 = 13.4
      radius A28 = 1.3
      distance A43 E11 = 1.5
      vertical: L1 V, L4 V, L7 V, L26 V, L39 V
      tangency: A1 L2, A2 L2, A1 L3, A2 L3, A3 L5, A4 L5, A3 L6, A4 L6, A31 L50, A31 L51, A29 L48, A29 L49, A30 L48, A30 L49, A32 L50, A28 L47, A28 L46, L47 A27, A27 L46, L45 A25, A25 L44, A26 L45, A26 L44
      coincidence: L6 L3, L51 L49, L50 L48
      symmetry: L1 L8 L7, L4 L9 L7, P4 P19 L7, P3 P20 L7, L2 L10 L7, P6 P21 L7, P5 P22 L7, L3 L11 L7, A1 A5 L7, A2 A6 L7, P10 P23 L7, P9 P24 L7, L5 L12 L7, P12 P25 L7, P11 P26 L7, L6 L13 L7, A3 A7 L7, A4 A8 L7, L1 L14 V, P3 P29 V, P4 P30 V, P5 P31 V, P6 P32 V, L4 L15 V, P9 P35 V, P10 P36 V, P11 P37 V, P12 P38 V, P13 P39 V, L8 L16 V, L9 L17 V, P19 P44 V, P20 P45 V, P21 P46 V, P22 P47 V, P23 P48 V, P24 P49 V, P25 P50 V, P26 P51 V, L2 L18 V, L3 L19 V, A1 A9 V, A2 A10 V, L5 L20 V, L6 L21 V, A3 A11 V, A4 A12 V, L10 L22 V, L11 L23 V, A5 A13 V, A6 A14 V, L12 L24 V, L13 L25 V, A7 A15 V, A8 A16 V, L1 L27 L26, L4 L28 L26, L8 L29 L26, L9 L30 L26, P4 P62 L26, P3 P63 L26, L2 L31 L26, P6 P64 L26, P5 P65 L26, L3 L32 L26, A1 A17 L26, A2 A18 L26, P10 P66 L26, P9 P67 L26, L5 L33 L26, P12 P68 L26, P11 P69 L26, L6 L34 L26, A3 A19 L26, A4 A20 L26, P19 P70 L26, P20 P71 L26, L10 L35 L26, P21 P72 L26, P22 P73 L26, L11 L36 L26, A5 A21 L26, A6 A22 L26, P23 P74 L26, P24 P75 L26, L12 L37 L26, P25 P76 L26, P26 P77 L26, L13 L38 L26, A7 A23 L26, A8 A24 L26, P53 P104 V, L40 L52 V, L41 L53 V, L42 L54 V, L43 L55 V, P88 P113 V, P89 P114 V, P90 P115 V, P91 P116 V, P92 P117 V, P93 P118 V, P94 P119 V, P95 P120 V, P96 P121 V, P97 P122 V, P98 P123 V, P99 P124 V, P100 P125 V, P101 P126 V, P102 P127 V, P103 P128 V, L44 L56 V, L45 L57 V, A25 A33 V, A26 A34 V, L46 L58 V, L47 L59 V, A27 A35 V, A28 A36 V, L48 L60 V, L49 L61 V, A29 A37 V, A30 A38 V, L50 L62 V, L51 L63 V, A31 A39 V, A32 A40 V, L64 L70 V, L65 L71 V, P133 P145 V, P134 P146 V, P135 P147 V, P136 P148 V, P137 P149 V, P138 P150 V, P139 P151 V, P140 P152 V, L66 L72 V, L67 L73 V, A41 A45 V, A42 A46 V, L68 L74 V, L69 L75 V, A43 A47 V, A44 A48 V
      parallelism: L47 L41
    Pocket5: profile Sketch8, direction (0, 0, 1), length 6.5, mirrored extent
    Sketch9 on yz-plane, origin (0, 0, 0), H (0, 1, 0), V (0, 0, 1)
      line L1 (-16.4, -2.8679) -> (16.4, -2.8679)
      line L2 (16.4, -2.8679) -> (16.4, -16.9664)
      line L3 (16.4, -16.9664) -> (-16.4, -16.9664)
      line L4 (-16.4, -16.9664) -> (-16.4, -2.8679)
      distance L2 L4 = 32.8
      distance L4 V = 16.4
      horizontal: L1 H, L3 H
      vertical: L2 V, L4 V
    Pocket6: profile Sketch9, direction (-1, 0, 0), length 79.5, mirrored extent, outer side
    Thickness2: Face (face of Pocket6 from Sketch9.L4; face of Pocket6 from Sketch9.L4), Thickness -6
    Sketch10 on end face of Pad3, origin (0, 0, -13), H (1, 0, 0), V (0, -1, 0)
      line L1 (57.5, -11.3284) -> (57.5, -23.6)
      point P1 (57.5, -11.3284)
      point P2 (57.5, -23.6)
      line L2 (44.5, -11.3284) -> (44.5, -23.6)
      point P3 (44.5, -11.3284)
      point P4 (44.5, -23.6)
      reference projected line E1 (60.75, 15) -> (60.75, -15) from edge [end face of Pad3 | face of Pad3 from Sketch7.L24]
      reference projected line E2 (47.75, 15) -> (47.75, -15) from edge [end face of Pad3 | face of Pad3 from Sketch7.L28]
      reference projected line E3 (58.8, 16.4) -> (60.75, 16.4) from edge [end face of Pad3 | face of Pocket6 from Sketch9.L4]
      reference projected line E4 (54.25, -11.3284) -> (60.75, -11.3284) from edge [face of Pad3 from Sketch7.L23 | end face of Pad3]
      reference intersected line E5 (47.75, -11.3284) -> (41.25, -11.3284) from face of Pad3 from Sketch7.L27
      point P5 (-57.5, -11.3284)
      point P6 (-57.5, -23.6)
      point P7 (-44.5, -11.3284)
      point P8 (-44.5, -23.6)
      line L3 (-57.5, -11.3284) -> (-57.5, -23.6)
      line L4 (-44.5, -11.3284) -> (-44.5, -23.6)
      line L5 (6.5, -11.3284) -> (6.5, -23.6)
      point P9 (6.5, -11.3284)
      point P10 (6.5, -23.6)
      reference projected line E6 (9.75, 15) -> (9.75, -15) from edge [end face of Pad3 | face of Pad3 from Sketch7.L55]
      point P11 (-6.5, -11.3284)
      point P12 (-6.5, -23.6)
      line L6 (-6.5, -11.3284) -> (-6.5, -23.6)
      line L7 (31.5, 23.6) -> (31.5, 11.3284)
      point P13 (31.5, 23.6)
      point P14 (31.5, 11.3284)
      reference projected line E7 (28.25, -16.4) -> (30.2, -16.4) from edge [face of Pocket6 from Sketch9.L2 | end face of Pad3]
      reference projected line E8 (28.25, 11.3284) -> (34.75, 11.3284) from edge [end face of Pad3 | face of Pad3 from Sketch7.L33]
      reference projected line E9 (28.25, 15) -> (28.25, -15) from edge [face of Pad3 from Sketch7.L36 | end face of Pad3]
      line L8 (18.5, 23.6) -> (18.5, 11.3284)
      point P15 (18.5, 23.6)
      point P16 (18.5, 11.3284)
      reference projected line E10 (21.75, 17.8284) -> (21.75, 11.3284) from edge [face of Pad3 from Sketch7.L29 | face of Pad3 from Sketch7.L30]
      point P17 (-31.5, 23.6)
      point P18 (-31.5, 11.3284)
      point P19 (-18.5, 23.6)
      point P20 (-18.5, 11.3284)
      line L9 (-31.5, 23.6) -> (-31.5, 11.3284)
      line L10 (-18.5, 23.6) -> (-18.5, 11.3284)
      distance L1 E1 = 3.25
      distance L2 E2 = 3.25
      distance E3 P2 = 40
      distance P4 P2 V = 0
      distance L5 E6 = 3.25
      distance P13 E7 = 40
      distance L7 E9 = 3.25
      distance L8 E10 = 3.25
      vertical: L1 V, L2 V, L5 V, L7 V, L8 V
      coincidence: P1 E4, P3 E5, P14 E8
